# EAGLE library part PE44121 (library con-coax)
SMB JACK RIGHT ANGLE SURFACE MOUNT Source: http://www.pasternack.com/Pdf/PE44121.pdf
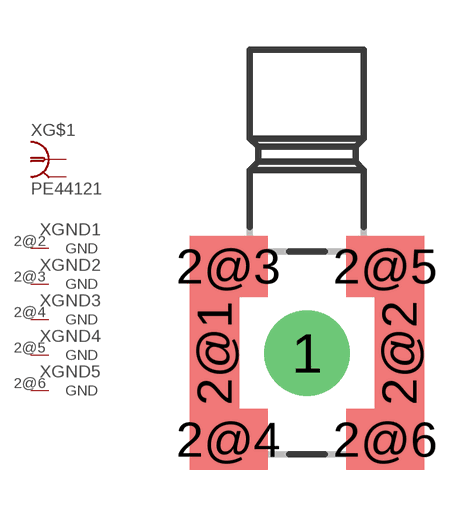
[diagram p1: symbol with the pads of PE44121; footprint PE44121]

Designator prefix X; gates G$1=BU-BNC GND1=PIN_GND GND2=PIN_GND GND3=PIN_GND GND4=PIN_GND GND5=PIN_GND

## PE44121 (OC_FARNELL: unknown; OC_NEWARK: unknown)  [PE44121]
1  G$1:1  pas
2@1  G$1:GND  pwr
2@2  GND1:GND  pwr
2@3  GND2:GND  pwr
2@4  GND3:GND  pwr
2@5  GND4:GND  pwr
2@6  GND5:GND  pwr

## Footprint PE44121 (pad centres in mm)
SMB JACK RIGHT ANGLE SURFACE MOUNT Source: http://www.pasternack.com/Pdf/PE44121.pdf
drill 1.727 pad 2.184 round: 1 0,0
smd 1.5 x 7.1: 2@1 -2.8,0; 2@2 2.8,0
smd 2.362 x 1.85: 2@3 -2.375,2.625; 2@4 -2.375,-2.625; 2@5 2.375,2.625; 2@6 2.375,-2.625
